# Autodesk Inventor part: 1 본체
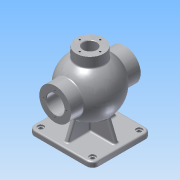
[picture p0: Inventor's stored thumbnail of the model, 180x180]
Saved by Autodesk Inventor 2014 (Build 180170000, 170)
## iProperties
Created: 2017-01
Part Number: 1 본체
Material: Aluminum 6061
Document SubType Name: Modeling
Designer: ksu
Density: 2.71 g/cm^3
Appearance: Aluminum - Flat
Mass: 1509.12 g
Surface Area: 1155.09 cm^2
Volume: 556.87 cm^3
Author: ksu
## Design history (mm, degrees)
sketch "Sketch1"
  geometry: C1 r 31 at (0, 0); 1 further point
  constraints: 1 centre point, 1 coincident
  dimensions: "d1" = 62 diameter of C1
extrude "Extrusion1" new body sketch "Sketch1" stored distance "d2" = 136; taper "d3" = 0 deg
workplane "Work Plane1"
sketch "Sketch2"
  geometry: L1 (-53, 0)-(53, 0); C1 r 31 at (0, 0) reference; A1 r 53 centre (0, 0) between (53, 0) and (-53, 0); 1 further point
  constraints: 2 end point, 2 point on circle, 1 centre point, 1 coincident, 1 horizontal
  dimensions: "d5" = 106 diameter of A1
revolve "Revolution1" sketch "Sketch2" stored, may be unused: angle "d6" = 90 deg
workplane "Work Plane2"
sketch "Sketch3"
  geometry: C1 r 27 at (0, 0); 1 further point
  constraints: 1 centre point, 1 coincident
  dimensions: "d8" = 54 diameter of C1
extrude "Extrusion2" join sketch "Sketch3" distance "d9" = 60; taper "d10" = 0 deg
sketch "Sketch4"
  geometry: L1 (-31, 42.988)-(-31, 68) reference; L2 (-31, 68)-(31, 68) reference; L3 (31, 68)-(31, 42.988) reference; L4 (45.607, 27)-(65, 27) reference; L5 (65, 27)-(65, -27) reference; L6 (65, -27)-(45.607, -27) reference; L7 (31, -42.988)-(31, -68) reference; L8 (31, -68)-(-31, -68) reference; L9 (-31, -68)-(-31, -42.988) reference; L10 (0, 68)-(17.5, 68); L11 (17.5, 68)-(17.5, 39.278); L12 (17.5, -39.278)-(17.5, -68); L13 (0, 68)-(0, -68); L14 (17.5, -68)-(0, -68); A1 r 53 centre (0, 0) between (-31, 42.988) and (-31, -42.988) reference; A2 r 53 centre (0, 0) between (45.607, 27) and (31, 42.988) reference; A3 r 53 centre (0, 0) between (31, -42.988) and (45.607, -27) reference; A4 r 43 centre (0, 0) between (17.5, -39.278) and (17.5, 39.278); 1 further point
  constraints: 10 end point, 2 collinear, 2 midpoint, 2 point on circle, 2 point on line, 1 centre point, 1 coincident, 1 perpendicular
  dimensions: "d11" = 17.5 distance of L10.start L10.end; "d12" = 86 diameter of A4
revolve "Revolution2" sketch "Sketch4" stored, may be unused: angle "d14" = 90 deg
sketch "Sketch5"
  geometry: C1 r 27 at (0, 0) reference; C2 r 13 at (0, 0)
  constraints: 1 centre point, 1 coincident
  dimensions: "d15" = 26 diameter of C2
extrude "Extrusion3" cut sketch "Sketch5" distance "d16" = 60; taper "d17" = 0 deg
workplane "Work Plane3"
sketch "Sketch6"
  geometry: L1 (-62.5, 57.5)-(62.5, 57.5); L2 (62.5, 57.5)-(62.5, -57.5); L3 (62.5, -57.5)-(-62.5, -57.5); L4 (-62.5, -57.5)-(-62.5, 57.5); L5 (-62.5, 57.5)-(62.5, -57.5); L6 (62.5, 57.5)-(-62.5, -57.5); 1 further point
  constraints: 12 end point, 2 midpoint, 2 parallel, 1 horizontal, 1 perpendicular
  dimensions: "d19" = 125 distance of L2.end L3.end; "d20" = 115 distance of L1.end L2.end
extrude "Extrusion4" join sketch "Sketch6" distance "d21" = 10; taper "d22" = 0 deg
sketch "Sketch7"
  geometry: L1 (-27, 45.607)-(-27, 65) reference; L2 (-27, 65)-(-13, 65) reference; L3 (-13, 65)-(-13, 40.988) reference; L4 (13, 40.988)-(13, 65) reference; L5 (13, 65)-(27, 65) reference; L6 (27, 65)-(27, 45.607) reference; L7 (62.5, -75)-(62.5, -85) reference; L8 (62.5, -85)-(-62.5, -85) reference; L9 (-62.5, -85)-(-62.5, -75) reference; L10 (-62.5, -75)-(62.5, -75) reference; L11 (-62.5, -75)-(-52.5, -75); L12 (-52.5, -75)-(-35.888, -33.885); L13 (62.5, -75)-(52.5, -75); L14 (52.5, -75)-(35.888, -33.885); L15 (-52.5, -75)-(-52.5, -44.76); A1 r 43 centre (0, 0) between (-13, 40.988) and (13, 40.988) reference; A2 r 53 centre (0, 0) between (-27, 45.607) and (27, 45.607) reference; A3 r 49.357 centre (0, 0) between (-35.888, -33.885) and (35.888, -33.885); 1 further point
  constraints: 10 end point, 2 point on circle, 2 point on line, 1 centre point, 1 coincident, 1 perpendicular
  dimensions: "d23" = 10 distance of L9.end L11.end; "d24" = 10 distance of L7.start L13.end; "d27" = 22 deg angle of L15 L12
extrude "Extrusion5" join sketch "Sketch7" stored distance "d29" = 8; taper "d30" = 0 deg
sketch "Sketch8"
  geometry: L1 (-17.5, -39.278)-(-17.5, -68) reference; L2 (-17.5, -68)-(-31, -68) reference; L3 (-31, -68)-(-31, -42.988) reference; L4 (-52.849, -4)-(-75, -4) reference; L5 (-75, -4)-(-75, -57.5) reference; L6 (-75, -57.5)-(-85, -57.5) reference; L7 (-85, -57.5)-(-85, 57.5) reference; L8 (-85, 57.5)-(-75, 57.5) reference; L9 (-75, 57.5)-(-75, 4) reference; L10 (-75, 4)-(-52.849, 4) reference; L11 (-31, 42.988)-(-31, 68) reference; L12 (-31, 68)-(-17.5, 68) reference; L13 (-17.5, 68)-(-17.5, 39.278) reference; L14 (45.607, 27)-(65, 27) reference; L15 (65, 27)-(65, 13) reference; L16 (65, 13)-(40.988, 13) reference; L17 (17.5, 39.278)-(17.5, 68) reference; L18 (17.5, 68)-(31, 68) reference; L19 (31, 68)-(31, 42.988) reference; L20 (65, -27)-(45.607, -27) reference; L21 (31, -42.988)-(31, -68) reference; L22 (31, -68)-(17.5, -68) reference; L23 (17.5, -68)-(17.5, -39.278) reference; L24 (40.988, -13)-(65, -13) reference; L25 (65, -13)-(65, -27) reference; L26 (-75, 57.5)-(-75, 47.5); L27 (-75, -57.5)-(-75, -47.5); L28 (-75, 47.5)-(-38.421, 32.721); L29 (-75, -47.5)-(-38.421, -32.721); A1 r 53 centre (0, 0) between (-52.849, -4) and (-31, -42.988) reference; A2 r 53 centre (0, 0) between (-31, 42.988) and (-52.849, 4) reference; A3 r 43 centre (0, 0) between (-17.5, 39.278) and (-17.5, -39.278) reference; A4 r 43 centre (0, 0) between (40.988, 13) and (17.5, 39.278) reference; A5 r 53 centre (0, 0) between (45.607, 27) and (31, 42.988) reference; A6 r 53 centre (0, 0) between (31, -42.988) and (45.607, -27) reference; A7 r 43 centre (0, 0) between (17.5, -39.278) and (40.988, -13) reference; A8 r 50.466 centre (0, 0) between (-38.421, 32.721) and (-38.421, -32.721); 1 further point
  constraints: 8 end point, 2 point on circle, 2 point on line, 1 centre point, 1 coincident
  dimensions: "d31" = 10 distance of L8.end L26.end; "d32" = 10 distance of L5.end L27.end
extrude "Extrusion6" join sketch "Sketch8" stored distance "d35" = 8; taper "d36" = 0 deg
sketch "Sketch9"
  geometry: L1 (62.5, 57.5)-(-62.5, 57.5) reference; L2 (-62.5, 57.5)-(-50.5, 57.5); L3 (62.5, 57.5)-(50.5, 57.5); L4 (-50.5, 57.5)-(-50.5, 45.5); L5 (50.5, 57.5)-(50.5, 45.5); L6 (0, 0)-(-40.261, 0); 4 further points
  constraints: 10 end point, 2 coincident, 2 perpendicular, 2 point on line, 2 symmetric about line, 1 parallel
  dimensions: "d37" = 12 distance of L1.end L2.end; "d38" = 12 distance of L1.start L3.end; "d40" = 12 distance of L2.end L4.end; "d41" = 12 distance of L3.end L5.end
hole "Hole1" sketch "Sketch9" at (-50.5, 45.5), (50.5, 45.5), (-50.5, -45.5), (50.5, -45.5) diameter "d42" = 8; stored, may be unused: countersink angle "d46" = 90 deg, drill point angle "d48" = 118 deg; dims "d43" = 6, "d44" = 12, "d45" = 3, "d47" = 8
sketch "Sketch10"
  geometry: C1 r 31 at (0, 0) reference; A1 r 22.5 centre (0, 0) between (0, 22.5) and (-22.5, 0); 2 further points
  constraints: 4 point on circle, 1 centre point, 1 coincident
  dimensions: "d49" = 45 diameter of A1
hole "Hole2" sketch "Sketch10" at (0, 22.5), (-22.5, 0), (0, -22.5), (22.5, 0) diameter "d50" = 3.459; stored, may be unused: countersink angle "d54" = 90 deg, drill point angle "d56" = 118 deg; dims "d51" = 12, "d52" = 4, "d53" = 2, "d55" = 15
sketch "Sketch11"
  geometry: C1 r 31 at (0, 0) reference; A1 r 24 centre (0, 0) between (0, 24) and (-24, 0); 2 further points
  constraints: 4 point on circle, 1 centre point, 1 coincident
  dimensions: "d57" = 48 diameter of A1
hole "Hole3" sketch "Sketch11" at (0, 24), (-24, 0), (0, -24), (24, 0) diameter "d58" = 3.459; stored, may be unused: countersink angle "d62" = 90 deg, drill point angle "d64" = 118 deg; dims "d59" = 16, "d60" = 4, "d61" = 2, "d63" = 19
sketch "Sketch12"
  geometry: L1 (-17.5, -39.278)-(-17.5, -68) reference; L2 (-17.5, -68)-(-22.271, -68) reference; L3 (-22.271, -68)-(-22.271, -49) reference; L4 (-22.271, -49)-(-24, -47.961) reference; L5 (-24, -47.961)-(-25.73, -49) reference; L6 (-25.73, -49)-(-25.73, -68) reference; L7 (-25.73, -68)-(-31, -68) reference; L8 (-31, -68)-(-31, -42.988) reference; L9 (-40.891, -33.719)-(-75, -47.5) reference; L10 (-75, -47.5)-(-75, -57.5) reference; L11 (-75, -57.5)-(-85, -57.5) reference; L12 (-85, -57.5)-(-85, 57.5) reference; L13 (-85, 57.5)-(-75, 57.5) reference; L14 (-75, 57.5)-(-75, 47.5) reference; L15 (-75, 47.5)-(-40.891, 33.719) reference; L16 (-31, 42.988)-(-31, 68) reference; L17 (-31, 68)-(-24.23, 68) reference; L18 (-24.23, 68)-(-24.23, 53) reference; L19 (-24.23, 53)-(-22.5, 51.961) reference; L20 (-22.5, 51.961)-(-20.77, 53) reference; L21 (-20.77, 53)-(-20.77, 68) reference; L22 (-20.77, 68)-(-17.5, 68) reference; L23 (-17.5, 68)-(-17.5, 39.278) reference; L24 (45.607, 27)-(65, 27) reference; L25 (65, 27)-(65, 13) reference; L26 (65, 13)-(40.988, 13) reference; L27 (17.5, 39.278)-(17.5, 68) reference; L28 (17.5, 68)-(20.77, 68) reference; L29 (20.77, 68)-(20.77, 53) reference; L30 (20.77, 53)-(22.5, 51.961) reference; L31 (22.5, 51.961)-(24.23, 53) reference; L32 (24.23, 53)-(24.23, 68) reference; L33 (24.23, 68)-(31, 68) reference; L34 (31, 68)-(31, 42.988) reference; L35 (65, -27)-(45.607, -27) reference; L36 (31, -42.988)-(31, -68) reference; L37 (31, -68)-(25.73, -68) reference; L38 (25.73, -68)-(25.73, -49) reference; L39 (25.73, -49)-(24, -47.961) reference; L40 (24, -47.961)-(22.271, -49) reference; L41 (22.271, -49)-(22.271, -68) reference; L42 (22.271, -68)-(17.5, -68) reference; L43 (17.5, -68)-(17.5, -39.278) reference; L44 (40.988, -13)-(65, -13) reference; L45 (65, -13)-(65, -27) reference; L46 (-17.5, -68)-(-17.5, -52); L47 (0, -52)-(-18.5, -52); L48 (-18.5, -52)-(-18.5, -50.25); L49 (-18.5, -50.25)-(0, -50.25); L50 (0, -50.25)-(0, -52); A1 r 53 centre (0, 0) between (-40.891, -33.719) and (-31, -42.988) reference; A2 r 53 centre (0, 0) between (-31, 42.988) and (-40.891, 33.719) reference; A3 r 43 centre (0, 0) between (-17.5, 39.278) and (-17.5, -39.278) reference; A4 r 43 centre (0, 0) between (40.988, 13) and (17.5, 39.278) reference; A5 r 53 centre (0, 0) between (45.607, 27) and (31, 42.988) reference; A6 r 53 centre (0, 0) between (31, -42.988) and (45.607, -27) reference; A7 r 43 centre (0, 0) between (17.5, -39.278) and (40.988, -13) reference; 1 further point
  constraints: 10 end point, 3 perpendicular, 1 parallel, 1 point on line
  dimensions: "d66" = 18.5 distance of L47.start L47.end; "d67" = 1.75 distance of L47.end L48.end
revolve "Revolution3" sketch "Sketch12" stored, may be unused: angle "d68" = 90 deg
chamfer "Chamfer1" distance "d69" = 1; stored, may be unused: second distance "d70" = 2, angle "d71" = 45 deg
chamfer "Chamfer2" distance "d72" = 1; stored, may be unused: second distance "d73" = 2, angle "d74" = 45 deg
chamfer "Chamfer3" distance "d75" = 1; stored, may be unused: second distance "d76" = 2, angle "d77" = 45 deg
fillet "Fillet1" dims "d78" = 3
fillet "Fillet2" dims "d79" = 3
fillet "Fillet3" dims "d80" = 12
fillet "Fillet4" dims "d81" = 3
fillet "Fillet6" dims "d83" = 3
fillet "Fillet7" dims "d84" = 3
workplane "Work Plane4"
sketch "Sketch13"
  geometry: L1 (75.042, -45.5)-(75.042, 45.5) reference; L2 (85, -52.831)-(78, -52.831) reference; L3 (85, 52.831)-(85, -52.831) reference; L4 (78, 52.831)-(85, 52.831) reference; L5 (-65, -27)-(-65, 27) reference; L6 (-65, -27)-(-65, 27) reference; L7 (-47.286, -27)-(-47.286, 27) reference; L8 (-65, 27)-(-47.286, 27) reference; L9 (-297.548, -49.638)-(-297.548, 49.638); L10 (-297.548, 49.638)-(187.548, 49.638); L11 (187.548, 49.638)-(187.548, -49.638); L12 (187.548, -49.638)-(-297.548, -49.638); 1 further point
  constraints: 4 other
emboss "Emboss1" sketch "Sketch13" dims "d87" = 0.5, "d88" = 0
sketch "Sketch14"
  geometry: C1 r 14 at (0, 0) reference; A1 r 20 centre (0, 0) between (0, 20) and (-20, 0); 2 further points
  constraints: 4 point on circle, 1 centre point, 1 coincident
  dimensions: "d89" = 40 diameter of A1
hole "Hole4" sketch "Sketch14" at (0, 20), (-20, 0), (0, -20), (20, 0) diameter "d90" = 3.459; stored, may be unused: countersink angle "d94" = 90 deg, drill point angle "d96" = 118 deg; dims "d91" = 9, "d92" = 4, "d93" = 2, "d95" = 11
fillet "Fillet8" dims "d97" = 2
body "Solid1"
node "Projected Loop1"
node "Project Cut Edges1"
node "Project Cut Edges2"
node "Project Cut Edges3"
node "Project Cut Edges4"
node "Project Cut Edges5"
node "Project Cut Edges6"
other parameters: "d4" = -68, "d7" = 65, "d18" = -85
